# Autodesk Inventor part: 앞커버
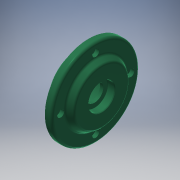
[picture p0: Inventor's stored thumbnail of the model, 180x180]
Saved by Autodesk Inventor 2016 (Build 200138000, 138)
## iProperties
Created: 2015-11
Part Number: 앞커버
Material: 알루미늄 6061
Document SubType Name: Modeling
Designer: mduedu
Density: 2.71 g/cm^3
Mass: 290.025 g
Surface Area: 234.647 cm^2
Volume: 107.02 cm^3
Appearance: 매끄러움 - 짙은 바다 녹색
Author: mduedu
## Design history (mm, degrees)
sketch "스케치1"
  geometry: C1 r 50 at (0, 0); 1 further point
  constraints: 1 centre point, 1 coincident
  dimensions: "d57" = 100 diameter of C1
extrude "돌출1" new body sketch "스케치1" distance "d3" = 8; taper "d4" = 0 deg
sketch "스케치2"
  geometry: C1 r 35 at (0, 0); 1 further point
  constraints: 1 centre point, 1 coincident
  dimensions: "d5" = 70 diameter of C1
extrude "돌출2" join sketch "스케치2" distance "d6" = 7; taper "d7" = -30 deg
sketch "스케치3" dims "d58" = 80
  geometry: 3 further points
  constraints: 2 vertical alignment, 1 coincident, 2 other
hole "구멍1" sketch "스케치3" at (0, 40) diameter "d11" = 4.5; stored, may be unused: countersink angle "d15" = 90 deg, drill point angle "d17" = 118 deg; dims "d12" = 6, "d13" = 8, "d14" = 4.4, "d16" = 8
sketch "스케치4"
  geometry: C1 r 35 at (0, 0); 1 further point
  constraints: 1 centre point, 1 coincident
  dimensions: "d21" = 70 diameter of C1
extrude "돌출3" join sketch "스케치4" distance "d23" = 12; taper "d24" = 0 deg
hole "구멍2" diameter "d27" = 30; stored, may be unused: countersink angle "d31" = 90 deg, drill point angle "d33" = 0 deg; dims "d25" = 10, "d26" = 10, "d28" = 6, "d29" = 40, "d30" = 12, "d32" = 15
fillet "모깎기3" dims "d36" = 3
fillet "모깎기4" dims "d37" = 3
fillet "모깎기5" dims "d38" = 0.3
chamfer "모따기1" distance "d39" = 1; stored, may be unused: second distance "d40" = 2, angle "d41" = 45 deg
hole "구멍3" diameter "d44" = 20; stored, may be unused: countersink angle "d48" = 90 deg, drill point angle "d50" = 118 deg; dims "d45" = 6, "d46" = 30, "d47" = 8.3, "d49" = 8, "d59" = 10, "d60" = 10
fillet "모깎기6" dims "d51" = 0.3
chamfer "모따기2" distance "d52" = 0.8; stored, may be unused: second distance "d53" = 2, angle "d54" = 30 deg
node "솔리드1"
pattern_circular "원형 패턴1" dims angle "d19" = 360 deg
